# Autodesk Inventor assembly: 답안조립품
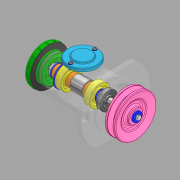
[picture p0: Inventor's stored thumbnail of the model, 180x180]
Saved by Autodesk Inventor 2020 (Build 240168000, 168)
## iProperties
Created: 2022-05
Part Number: 답안조립품
Document SubType Name: Assembly
Designer: User
Author: User
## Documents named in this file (22)
- C:\Users\User\Desktop\720506V1030\답안조립품.iam
- C:\Users\User\Desktop\720506V1030\본체.ipt
- C:\Users\User\Desktop\720506V1030\멈춤링 15 x 1.ipt
- C:\Users\User\Desktop\720506V1030\멈춤링 35 x 1.6.ipt
- C:\Users\User\Desktop\720506V1030\베어링 6202.ipt
- C:\Users\User\Desktop\720506V1030\볼트 M4 x 10.ipt
- C:\Users\User\Desktop\720506V1030\부시1.ipt
- C:\Users\User\Desktop\720506V1030\부시2.ipt
- C:\Users\User\Desktop\720506V1030\사이드 커버.ipt
- 사이드 커버.ipt
- C:\Users\User\Desktop\720506V1030\십자볼트 M3 x 10.ipt
- C:\Users\User\Desktop\720506V1030\오일 실 15 x 30 x 7.ipt
- C:\Users\User\Desktop\720506V1030\와셔 3 x 6.ipt
- C:\Users\User\Desktop\720506V1030\와셔 4 x 16.ipt
- C:\Users\User\Desktop\720506V1030\와셔 10 x 21.ipt
- C:\Users\User\Desktop\720506V1030\축.ipt
- C:\Users\User\Desktop\720506V1030\키 4 x 4.ipt
- C:\Users\User\Desktop\720506V1030\탑 커버.ipt
- C:\Users\User\Desktop\720506V1030\V-벨트풀리.ipt
- C:\Users\User\Desktop\720506V1030\너트 M10.ipt
- C:\Users\User\Desktop\720506V1030\개스킷.ipt
- C:\Users\User\Desktop\720506V1030\멈춤나사 M3.ipt
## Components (3 placed, 3 different names)
1. V-벨트풀리:1 — 각도:6
2. ISO 4017 M4 x 10:2 — 각도:2
3. 개스킷:1
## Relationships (2: Angle 2)
- 각도:2 [Angle]: ISO 4017 M4 x 10:2
- 각도:6 [Angle]: V-벨트풀리:1
